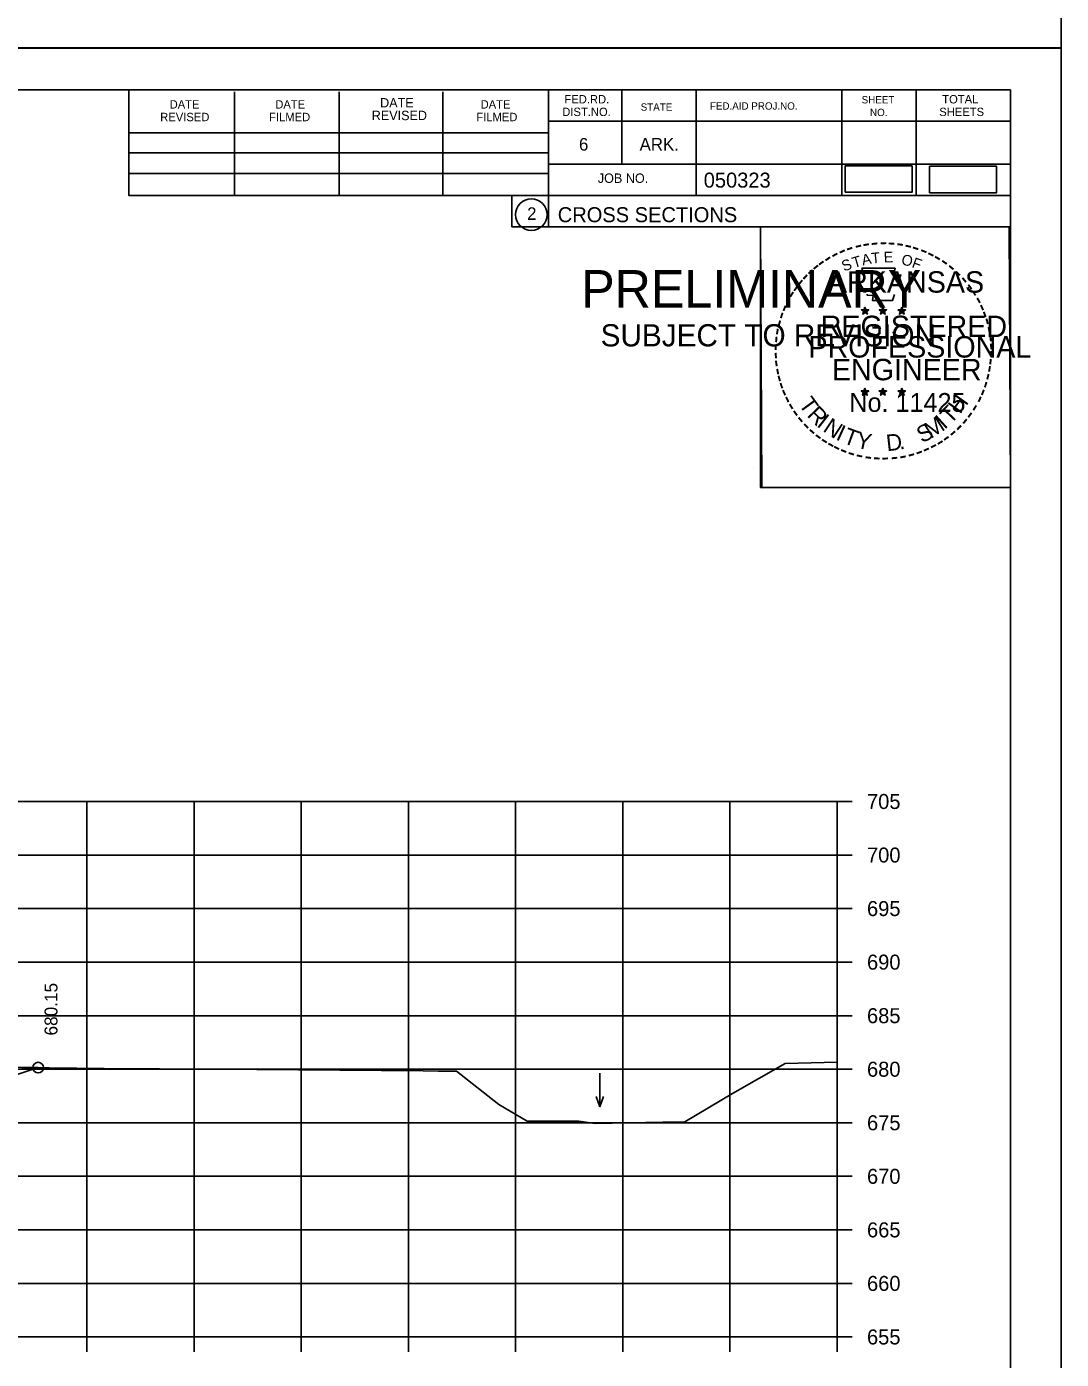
# Model space of a CAD drawing. Extents: x 1360146 to 1361431, y 631444 to 632352.
# Drawn here: x 1360383.1 to 1360479.7, y 631961.7 to 632086.2 of the extents above; entities that cross this region are included whole.
import ezdxf

# ---------------------------------------------------------------- set-up
doc = ezdxf.new("R2010")
doc.units = 0
for name, color, linetype in [('Default', 7, 'Continuous'), ('R_Axis', 7, 'Continuous'), ('R_Axis Annot', 7, 'Continuous'), ('R_Border', 7, 'Continuous'), ('R_Border PE', 7, 'Continuous'), ('R_Border Prem', 7, 'Continuous'), ('R_Exist Surface', 7, 'Continuous'), ('R_Fin Surface', 7, 'Continuous'), ('R_Grid', 7, 'Continuous'), ('R_No Plot', 7, 'Continuous'), ('R_Water Annot', 7, 'Continuous'), ('R_Xsect Elev', 7, 'Continuous')]:
    doc.layers.add(name, color=color, linetype=linetype)

msp = doc.modelspace()

# ---------------------------------------------------------------- linework, layer by layer
at = {"layer": 'Default'}
for points in [[(1360459.52, 632070.7), (1360465.77, 632070.7), (1360465.77, 632073.17), (1360459.52, 632073.17)], [(1360467.41, 632070.66), (1360473.66, 632070.66), (1360473.66, 632073.14), (1360467.41, 632073.14)]]:
    msp.add_lwpolyline(points, close=True, dxfattribs=at)
at = {"layer": 'R_Axis'}
for p, q in [((1360458.77, 631963.82), (1360458.77, 632013.82)), ((1360460.17, 632013.82), (1360458.77, 632013.82)), ((1360460.17, 632008.82), (1360458.77, 632008.82)), ((1360460.17, 632003.82), (1360458.77, 632003.82)), ((1360460.17, 631998.82), (1360458.77, 631998.82)), ((1360460.17, 631993.82), (1360458.77, 631993.82)), ((1360460.17, 631988.82), (1360458.77, 631988.82)), ((1360460.17, 631983.82), (1360458.77, 631983.82)), ((1360460.17, 631978.82), (1360458.77, 631978.82)), ((1360460.17, 631973.82), (1360458.77, 631973.82)), ((1360460.17, 631968.82), (1360458.77, 631968.82)), ((1360178.77, 631963.82), (1360458.77, 631963.82)), ((1360388.77, 631962.42), (1360388.77, 631963.82)), ((1360398.77, 631962.42), (1360398.77, 631963.82)), ((1360408.77, 631962.42), (1360408.77, 631963.82)), ((1360418.77, 631962.42), (1360418.77, 631963.82)), ((1360428.77, 631962.42), (1360428.77, 631963.82)), ((1360438.77, 631962.42), (1360438.77, 631963.82)), ((1360448.77, 631962.42), (1360448.77, 631963.82)), ((1360458.77, 631962.42), (1360458.77, 631963.82)), ((1360460.17, 631963.82), (1360458.77, 631963.82))]:
    msp.add_line(p, q, dxfattribs=at)
at = {"layer": 'R_Border'}
for p, q in [((1360158.77, 632080.28), (1360474.95, 632080.28)), ((1360392.69, 632070.4), (1360392.69, 632080.28)), ((1360402.55, 632070.4), (1360402.55, 632080.08)), ((1360412.31, 632070.4), (1360412.31, 632080.08)), ((1360421.99, 632070.4), (1360421.99, 632080.08)), ((1360431.85, 632080.28), (1360431.85, 632067.48)), ((1360438.69, 632080.28), (1360438.69, 632073.34)), ((1360445.63, 632080.28), (1360445.63, 632070.4)), ((1360459.21, 632080.28), (1360459.21, 632070.4)), ((1360466.15, 632080.28), (1360466.15, 632070.4)), ((1360474.95, 631874.82), (1360474.95, 632080.28)), ((1360474.95, 632077.34), (1360431.85, 632077.34)), ((1360474.95, 632077.36), (1360474.95, 632077.36)), ((1360392.69, 632076.26), (1360431.85, 632076.26)), ((1360392.69, 632074.4), (1360431.85, 632074.4)), ((1360474.95, 632073.34), (1360431.85, 632073.34)), ((1360434.81, 632073.34), (1360474.95, 632073.34)), ((1360392.69, 632070.4), (1360392.69, 632072.46)), ((1360392.69, 632072.46), (1360431.85, 632072.46)), ((1360474.95, 632070.4), (1360392.69, 632070.4)), ((1360431.85, 632067.48), (1360474.95, 632067.48))]:
    msp.add_line(p, q, dxfattribs=at)
msp.add_circle((1360430.24, 632068.62), 1.47, dxfattribs=at)
at = {"layer": 'R_Border PE'}
for p, q in [((1360461.04, 632059.74), (1360461.38, 632059.62)), ((1360461.04, 632059.74), (1360461.29, 632059.69)), ((1360461.04, 632059.74), (1360461.27, 632059.61)), ((1360461.17, 632059.33), (1360461.38, 632059.62)), ((1360461.17, 632059.33), (1360461.29, 632059.57)), ((1360461.38, 632059.99), (1360461.34, 632059.74)), ((1360461.38, 632059.62), (1360461.38, 632059.99)), ((1360461.38, 632059.99), (1360461.43, 632059.74)), ((1360461.73, 632059.74), (1360461.38, 632059.62)), ((1360461.6, 632059.33), (1360461.38, 632059.62)), ((1360461.73, 632059.74), (1360461.45, 632059.69)), ((1360461.6, 632059.33), (1360461.46, 632059.62)), ((1360461.73, 632059.74), (1360461.53, 632059.63)), ((1360462.71, 632059.74), (1360463.05, 632059.62)), ((1360462.71, 632059.74), (1360462.96, 632059.69)), ((1360462.71, 632059.74), (1360462.94, 632059.61)), ((1360462.84, 632059.33), (1360463.05, 632059.62)), ((1360462.84, 632059.33), (1360462.96, 632059.57)), ((1360463.05, 632059.99), (1360463.01, 632059.74)), ((1360463.05, 632059.62), (1360463.05, 632059.99)), ((1360463.05, 632059.99), (1360463.1, 632059.74)), ((1360463.4, 632059.74), (1360463.05, 632059.62)), ((1360463.27, 632059.33), (1360463.05, 632059.62)), ((1360463.4, 632059.74), (1360463.12, 632059.69)), ((1360463.27, 632059.33), (1360463.13, 632059.62)), ((1360463.4, 632059.74), (1360463.2, 632059.63)), ((1360464.47, 632059.72), (1360464.82, 632059.61)), ((1360464.47, 632059.72), (1360464.72, 632059.68)), ((1360464.47, 632059.72), (1360464.71, 632059.6)), ((1360464.6, 632059.32), (1360464.82, 632059.61)), ((1360464.6, 632059.32), (1360464.73, 632059.56)), ((1360464.82, 632059.98), (1360464.78, 632059.73)), ((1360464.82, 632059.61), (1360464.82, 632059.98)), ((1360464.82, 632059.98), (1360464.87, 632059.73)), ((1360465.17, 632059.72), (1360464.82, 632059.61)), ((1360465.03, 632059.32), (1360464.82, 632059.61)), ((1360465.17, 632059.72), (1360464.88, 632059.67)), ((1360465.03, 632059.32), (1360464.89, 632059.61)), ((1360465.17, 632059.72), (1360464.96, 632059.62)), ((1360461.17, 632059.33), (1360461.38, 632059.54)), ((1360461.6, 632059.33), (1360461.38, 632059.54)), ((1360462.84, 632059.33), (1360463.05, 632059.54)), ((1360463.27, 632059.33), (1360463.05, 632059.54)), ((1360464.6, 632059.32), (1360464.82, 632059.53)), ((1360465.03, 632059.32), (1360464.82, 632059.53)), ((1360461.03, 632052.16), (1360461.38, 632052.05)), ((1360461.03, 632052.16), (1360461.28, 632052.12)), ((1360461.03, 632052.16), (1360461.27, 632052.04)), ((1360461.38, 632052.42), (1360461.34, 632052.16)), ((1360461.38, 632052.05), (1360461.38, 632052.42)), ((1360461.38, 632052.42), (1360461.43, 632052.17)), ((1360461.73, 632052.16), (1360461.38, 632052.05)), ((1360461.73, 632052.16), (1360461.44, 632052.11)), ((1360461.73, 632052.16), (1360461.52, 632052.06)), ((1360462.7, 632052.16), (1360463.05, 632052.05)), ((1360462.7, 632052.16), (1360462.95, 632052.12)), ((1360462.7, 632052.16), (1360462.94, 632052.04)), ((1360463.05, 632052.42), (1360463.01, 632052.16)), ((1360463.05, 632052.05), (1360463.05, 632052.42)), ((1360463.05, 632052.42), (1360463.1, 632052.17)), ((1360463.4, 632052.16), (1360463.05, 632052.05)), ((1360463.4, 632052.16), (1360463.11, 632052.11)), ((1360463.4, 632052.16), (1360463.19, 632052.06)), ((1360464.47, 632052.15), (1360464.82, 632052.04)), ((1360464.47, 632052.15), (1360464.72, 632052.11)), ((1360464.47, 632052.15), (1360464.7, 632052.03)), ((1360464.82, 632052.41), (1360464.78, 632052.15)), ((1360464.82, 632052.04), (1360464.82, 632052.41)), ((1360464.82, 632052.41), (1360464.87, 632052.16)), ((1360465.16, 632052.15), (1360464.82, 632052.04)), ((1360465.16, 632052.15), (1360464.88, 632052.1)), ((1360465.16, 632052.15), (1360464.96, 632052.05)), ((1360461.16, 632051.75), (1360461.38, 632052.05)), ((1360461.16, 632051.75), (1360461.29, 632052)), ((1360461.16, 632051.75), (1360461.38, 632051.97)), ((1360461.59, 632051.75), (1360461.38, 632052.05)), ((1360461.59, 632051.75), (1360461.38, 632051.97)), ((1360461.59, 632051.75), (1360461.46, 632052.05)), ((1360462.83, 632051.75), (1360463.05, 632052.05)), ((1360462.83, 632051.75), (1360462.96, 632052)), ((1360462.83, 632051.75), (1360463.05, 632051.97)), ((1360463.26, 632051.75), (1360463.05, 632052.05)), ((1360463.26, 632051.75), (1360463.05, 632051.97)), ((1360463.26, 632051.75), (1360463.13, 632052.05)), ((1360464.6, 632051.74), (1360464.82, 632052.04)), ((1360464.6, 632051.74), (1360464.73, 632051.99)), ((1360464.6, 632051.74), (1360464.81, 632051.96)), ((1360465.03, 632051.74), (1360464.81, 632051.96)), ((1360465.03, 632051.74), (1360464.82, 632052.04)), ((1360465.03, 632051.74), (1360464.89, 632052.04))]:
    msp.add_line(p, q, dxfattribs=at)
for points in [[(1360461.08, 632063.61), (1360461.35, 632062.79)], [(1360464.59, 632062.69), (1360464.73, 632062.98), (1360464.04, 632062.95), (1360464.19, 632063.61), (1360461.08, 632063.61)], [(1360461.57, 632061.19), (1360461.57, 632061.1), (1360462.13, 632061.08), (1360462.08, 632060.61), (1360463.95, 632060.61), (1360464.15, 632061.15)], [(1360461.38, 632059.99), (1360461.6, 632059.33), (1360461.04, 632059.74), (1360461.73, 632059.74), (1360461.17, 632059.33), (1360461.38, 632059.99)], [(1360463.05, 632059.99), (1360463.27, 632059.33), (1360462.71, 632059.74), (1360463.4, 632059.74), (1360462.84, 632059.33), (1360463.05, 632059.99)], [(1360464.82, 632059.98), (1360465.03, 632059.32), (1360464.47, 632059.72), (1360465.17, 632059.72), (1360464.6, 632059.32), (1360464.82, 632059.98)], [(1360461.38, 632052.42), (1360461.59, 632051.75), (1360461.03, 632052.16), (1360461.73, 632052.16), (1360461.16, 632051.75), (1360461.38, 632052.42)], [(1360463.05, 632052.42), (1360463.26, 632051.75), (1360462.7, 632052.16), (1360463.4, 632052.16), (1360462.83, 632051.75), (1360463.05, 632052.42)], [(1360464.82, 632052.41), (1360465.03, 632051.74), (1360464.47, 632052.15), (1360465.16, 632052.15), (1360464.6, 632051.74), (1360464.82, 632052.41)]]:
    msp.add_lwpolyline(points, dxfattribs=at)
for centre, radius in [((1360461.38, 632059.62), 0.172), ((1360461.38, 632059.62), 0.145), ((1360461.38, 632059.62), 0.116), ((1360461.38, 632059.62), 0.0991), ((1360461.38, 632059.62), 0.0747), ((1360461.38, 632059.62), 0.0495), ((1360461.38, 632059.62), 0.0296), ((1360463.05, 632059.62), 0.172), ((1360463.05, 632059.62), 0.145), ((1360463.05, 632059.62), 0.116), ((1360463.05, 632059.62), 0.0991), ((1360463.05, 632059.62), 0.0747), ((1360463.05, 632059.62), 0.0495), ((1360463.05, 632059.62), 0.0296), ((1360464.82, 632059.61), 0.172), ((1360464.82, 632059.61), 0.145), ((1360464.82, 632059.61), 0.116), ((1360464.82, 632059.61), 0.0991), ((1360464.82, 632059.61), 0.0747), ((1360464.82, 632059.61), 0.0495), ((1360464.82, 632059.61), 0.0296), ((1360461.38, 632052.05), 0.172), ((1360461.38, 632052.05), 0.145), ((1360461.38, 632052.05), 0.116), ((1360461.38, 632052.05), 0.0991), ((1360461.38, 632052.05), 0.0747), ((1360461.38, 632052.05), 0.0495), ((1360463.05, 632052.05), 0.172), ((1360463.05, 632052.05), 0.145), ((1360463.05, 632052.05), 0.116), ((1360463.05, 632052.05), 0.0991), ((1360463.05, 632052.05), 0.0747), ((1360463.05, 632052.05), 0.0495), ((1360464.82, 632052.04), 0.172), ((1360464.82, 632052.04), 0.145), ((1360464.82, 632052.04), 0.116), ((1360464.82, 632052.04), 0.0991), ((1360464.82, 632052.04), 0.0747), ((1360461.38, 632052.05), 0.0296), ((1360463.05, 632052.05), 0.0296), ((1360464.82, 632052.04), 0.0495), ((1360464.82, 632052.04), 0.0296)]:
    msp.add_circle(centre, radius, dxfattribs=at)
at = {"layer": 'R_Exist Surface'}
msp.add_lwpolyline([(1360372.41, 631989.11), (1360390.37, 631988.9), (1360400.73, 631988.82), (1360420.15, 631988.66), (1360421.56, 631988.64), (1360423.27, 631988.65), (1360427.22, 631985.53), (1360429.85, 631983.96), (1360434.69, 631983.96), (1360436.21, 631983.76), (1360442.5, 631983.88), (1360444.58, 631983.91), (1360449.01, 631986.55), (1360453.94, 631989.37), (1360458.77, 631989.49)], dxfattribs=at)
at = {"layer": 'R_Fin Surface'}
msp.add_lwpolyline([(1360242.28, 631987.92), (1360261.78, 631981.42), (1360298.75, 631993.74), (1360298.77, 631993.75), (1360304.77, 631995.25), (1360308.77, 631994.95), (1360318.77, 631994.19), (1360328.77, 631993.42), (1360332.77, 631993.12), (1360338.55, 631991.67), (1360338.77, 631991.62), (1360365.47, 631982.72), (1360384.22, 631988.97)], dxfattribs=at)
at = {"layer": 'R_Grid'}
for p, q in [((1360178.77, 632013.82), (1360458.77, 632013.82)), ((1360388.77, 631963.82), (1360388.77, 632013.82)), ((1360398.77, 631963.82), (1360398.77, 632013.82)), ((1360408.77, 631963.82), (1360408.77, 632013.82)), ((1360418.77, 631963.82), (1360418.77, 632013.82)), ((1360428.77, 631963.82), (1360428.77, 632013.82)), ((1360438.77, 631963.82), (1360438.77, 632013.82)), ((1360448.77, 631963.82), (1360448.77, 632013.82)), ((1360458.77, 631963.82), (1360458.77, 632013.82)), ((1360178.77, 632008.82), (1360458.77, 632008.82)), ((1360178.77, 632003.82), (1360458.77, 632003.82)), ((1360178.77, 631998.82), (1360458.77, 631998.82)), ((1360178.77, 631993.82), (1360458.77, 631993.82)), ((1360178.77, 631988.82), (1360458.77, 631988.82)), ((1360178.77, 631983.82), (1360458.77, 631983.82)), ((1360178.77, 631978.82), (1360458.77, 631978.82)), ((1360178.77, 631973.82), (1360458.77, 631973.82)), ((1360178.77, 631968.82), (1360458.77, 631968.82)), ((1360178.77, 631963.82), (1360458.77, 631963.82))]:
    msp.add_line(p, q, dxfattribs=at)
at = {"layer": 'R_No Plot'}
for p, q in [((1360146.37, 632084.18), (1360479.7, 632084.18)), ((1360146.37, 632084.17), (1360479.7, 632084.17)), ((1360450.99, 632045.02), (1360450.99, 632045.02))]:
    msp.add_line(p, q, dxfattribs=at)
for points in [[(1360146.36, 632297.51), (1360479.7, 632297.51), (1360479.7, 632084.17), (1360146.36, 632084.17)], [(1360146.36, 632084.17), (1360479.7, 632084.17), (1360479.7, 631870.84), (1360146.36, 631870.84)], [(1360392.69, 632080.28), (1360392.69, 632070.4), (1360428.42, 632070.4), (1360428.42, 632067.48), (1360451.62, 632067.48), (1360451.62, 632043.15), (1360474.95, 632043.15), (1360474.95, 631874.82), (1360158.77, 631874.82), (1360158.77, 632080.28)], [(1360451.62, 632067.48), (1360474.83, 632067.48), (1360474.95, 632043.15), (1360451.74, 632043.15)], [(1360348.56, 631988.36), (1360350.29, 631988.65), (1360365.94, 631989.14), (1360372.41, 631989.11), (1360384.22, 631988.97), (1360365.47, 631982.72)]]:
    msp.add_lwpolyline(points, close=True, dxfattribs=at)
msp.add_circle((1360384.22, 631988.97), 0.5, dxfattribs=at)
at = {"layer": 'R_Water Annot'}
for p, q in [((1360436.63, 631988.44), (1360436.63, 631985.3)), ((1360436.63, 631985.3), (1360436.28, 631986.26)), ((1360436.63, 631985.3), (1360436.98, 631986.26))]:
    msp.add_line(p, q, dxfattribs=at)

# ---------------------------------------------------------------- texts
at = {"layer": 'R_Axis Annot'}
for s, p in [('705', (1360461.57, 632013.12)), ('700', (1360461.57, 632008.12)), ('695', (1360461.57, 632003.12)), ('690', (1360461.57, 631998.12)), ('685', (1360461.57, 631993.12)), ('680', (1360461.57, 631988.12)), ('675', (1360461.57, 631983.12)), ('670', (1360461.57, 631978.12)), ('665', (1360461.57, 631973.12)), ('660', (1360461.57, 631968.12)), ('655', (1360461.57, 631963.12))]:
    msp.add_text(s, height=1.4, dxfattribs=at).set_placement(p)
at = {"layer": 'R_Border'}
for s, height, p in [('DATE', 0.879, (1360416.13, 632078.62)), ('FED.RD.', 0.782, (1360433.33, 632079)), ('SHEET', 0.684, (1360461.07, 632079)), ('TOTAL', 0.782, (1360468.59, 632079)), ('DATE', 0.782, (1360396.49, 632078.52)), ('DATE', 0.782, (1360406.35, 632078.52)), ('REVISED', 0.879, (1360415.35, 632077.44)), ('DATE', 0.782, (1360425.51, 632078.52)), ('DIST.NO.', 0.782, (1360433.13, 632077.82)), ('STATE', 0.684, (1360440.45, 632078.32)), ('FED.AID PROJ.NO.', 0.684, (1360446.91, 632078.42)), ('NO.', 0.684, (1360461.85, 632077.82)), ('SHEETS', 0.782, (1360468.31, 632077.82)), ('REVISED', 0.782, (1360395.61, 632077.34)), ('FILMED', 0.782, (1360405.77, 632077.34)), ('FILMED', 0.782, (1360425.11, 632077.34)), ('6', 1.17, (1360434.69, 632074.6)), ('ARK.', 1.172, (1360440.35, 632074.6)), ('JOB NO.', 0.879, (1360436.45, 632071.58)), ('050323', 1.4, (1360446.33, 632071.14)), ('2', 1.17, (1360429.85, 632068.13)), ('CROSS SECTIONS', 1.4, (1360432.71, 632067.91))]:
    msp.add_text(s, height=height, rotation=360, dxfattribs=at).set_placement(p)
at = {"layer": 'R_Border PE'}
for s, height, rotation, p in [('-', 1.6, 13.6301, (1360460.57, 632064.98)), ('-', 1.6, 10.2193, (1360461.25, 632065.14)), ('-', 1.6, 5.8968, (1360461.98, 632065.25)), ('-', 1.6, 0.1862, (1360462.75, 632065.33)), ('-', 1.6, 357.743, (1360463.48, 632065.31)), ('-', 1.6, 352.1617, (1360464.22, 632065.26)), ('-', 1.6, 347.2049, (1360464.94, 632065.14)), ('-', 1.6, 34.0636, (1360457.96, 632063.78)), ('-', 1.6, 28.7918, (1360458.56, 632064.15)), ('-', 1.6, 24.3072, (1360459.19, 632064.47)), ('-', 1.6, 19.1761, (1360459.82, 632064.74)), ('T', 1, 16.4036, (1360460.35, 632063.62)), ('A', 1, 11.2132, (1360461.17, 632063.87)), ('T', 1, 6.0228, (1360462.02, 632064.04)), ('E', 1, 0.8323, (1360463.13, 632064.15)), ('O', 1, 350.4515, (1360464.73, 632063.94)), ('F', 1, 340.0707, (1360465.68, 632063.71)), ('-', 1.6, 342.3362, (1360465.57, 632064.99)), ('-', 1.6, 337.8551, (1360466.31, 632064.76)), ('-', 1.6, 334.1211, (1360466.94, 632064.49)), ('-', 1.6, 329.6409, (1360467.52, 632064.21)), ('-', 1.6, 42.9622, (1360456.47, 632062.59)), ('-', 1.6, 38.9507, (1360456.91, 632063.01)), ('-', 1.6, 36.2317, (1360457.38, 632063.39)), ('ARKANSAS', 2, 360, (1360457.93, 632061.33)), ('S', 1, 21.594, (1360459.43, 632063.29)), ('-', 1.6, 325.8627, (1360468.16, 632063.85)), ('-', 1.6, 320.5297, (1360468.77, 632063.42)), ('-', 1.6, 315.5786, (1360469.37, 632062.94)), ('-', 1.6, 50.6142, (1360455.62, 632061.63)), ('-', 1.6, 48.423, (1360456.03, 632062.12)), ('-', 1.6, 309.8797, (1360469.94, 632062.39)), ('-', 1.6, 306.6522, (1360470.47, 632061.78)), ('-', 1.6, 58.0706, (1360454.88, 632060.54)), ('-', 1.6, 54.2325, (1360455.21, 632061.06)), ('-', 1.4, 303.6753, (1360470.95, 632061.22)), ('-', 1.6, 299.6684, (1360471.27, 632060.61)), ('-', 1.6, 67.7743, (1360454.31, 632059.31)), ('-', 1.6, 62.8713, (1360454.57, 632059.92)), ('DWB', 0.01, 360, (1360461.37, 632059.62)), ('DWB', 0.01, 360, (1360463.04, 632059.62)), ('DWB', 0.01, 360, (1360464.81, 632059.61)), ('-', 1.6, 294.6628, (1360471.59, 632060)), ('-', 1.6, 290.5728, (1360471.85, 632059.42)), ('-', 1.6, 75.461, (1360453.9, 632057.97)), ('-', 1.6, 72.3945, (1360454.09, 632058.68)), ('REGISTERED', 2, 360, (1360457.25, 632057.18)), ('-', 1.6, 285.1233, (1360472.09, 632058.84)), ('-', 1.6, 85.1863, (1360453.69, 632056.56)), ('-', 1.6, 81.2013, (1360453.76, 632057.25)), ('PROFESSIONAL', 2, 360, (1360456.1, 632055.27)), ('-', 1.6, 280.5493, (1360472.29, 632058.1)), ('-', 1.6, 276.5962, (1360472.45, 632057.33)), ('-', 1.6, 89.0622, (1360453.66, 632055.86)), ('-', 1.6, 274.3301, (1360472.51, 632056.61)), ('-', 1.6, 269.9407, (1360472.54, 632055.98)), ('-', 1.6, 94.1959, (1360453.7, 632055.14)), ('-', 1.6, 98.9479, (1360453.77, 632054.47)), ('ENGINEER', 2, 360, (1360458.29, 632053.15)), ('-', 1.6, 263.5172, (1360472.52, 632055.31)), ('-', 1.6, 101.7149, (1360453.91, 632053.74)), ('-', 1.6, 105.4578, (1360454.07, 632053.14)), ('-', 1.6, 255.7626, (1360472.34, 632053.98)), ('-', 1.6, 260.9953, (1360472.45, 632054.66)), ('-', 1.6, 109.0874, (1360454.28, 632052.51)), ('-', 1.6, 114.0643, (1360454.54, 632051.92)), ('-', 1.6, 247.8887, (1360471.94, 632052.58)), ('-', 1.6, 252.8681, (1360472.16, 632053.26)), ('-', 1.6, 115.7289, (1360454.84, 632051.3)), ('-', 1.6, 120.4471, (1360455.2, 632050.71)), ('T', 1.54, 306.0406, (1360455.14, 632050.89)), ('No. 11425', 1.757, 360, (1360459.92, 632050.2)), ('DWB', 0.01, 360, (1360461.37, 632052.05)), ('DWB', 0.01, 360, (1360463.04, 632052.05)), ('DWB', 0.01, 360, (1360464.8, 632052.04)), ('T', 1.54, 46.6444, (1360469.37, 632048.98)), ('H', 1.54, 54.6088, (1360470.26, 632049.92)), ('-', 1.6, 239.0712, (1360471.28, 632051.2)), ('-', 1.6, 244.6197, (1360471.68, 632051.96)), ('-', 1.6, 125.8934, (1360455.6, 632050.15)), ('-', 1.6, 130.7181, (1360456.06, 632049.6)), ('R', 1.54, 314.005, (1360455.9, 632049.84)), ('I', 1.54, 321.9694, (1360456.8, 632048.91)), ('N', 1.54, 326.5002, (1360457.37, 632048.44)), ('M', 1.54, 32.6563, (1360467.52, 632047.66)), ('I', 1.54, 42.1136, (1360468.81, 632048.5)), ('-', 1.6, 233.8452, (1360470.88, 632050.55)), ('-', 1.6, 134.2238, (1360456.58, 632049.05)), ('-', 1.6, 138.9338, (1360457.11, 632048.59)), ('I', 1.54, 335.3603, (1360458.58, 632047.65)), ('T', 1.54, 339.8912, (1360459.24, 632047.32)), ('Y', 1.54, 347.8556, (1360460.46, 632046.88)), ('S', 1.54, 26.9312, (1360466.69, 632047.25)), ('-', 1.6, 221.0851, (1360469.45, 632048.91)), ('-', 1.6, 225.7653, (1360469.97, 632049.42)), ('-', 1.6, 231.2538, (1360470.45, 632049.98)), ('-', 1.6, 144.6463, (1360457.66, 632048.18)), ('-', 1.6, 148.0898, (1360458.22, 632047.81)), ('-', 1.6, 151.5704, (1360458.8, 632047.49)), ('D', 1.54, 6.3969, (1360463.44, 632046.52)), ('-', 1.6, 207.3568, (1360467.81, 632047.71)), ('-', 1.6, 212.2491, (1360468.37, 632048.05)), ('-', 1.6, 215.7363, (1360468.9, 632048.44)), ('-', 1.6, 154.6002, (1360459.32, 632047.24)), ('-', 1.6, 158.5612, (1360459.95, 632046.99)), ('-', 1.6, 162.7983, (1360460.63, 632046.77)), ('-', 1.6, 167.5555, (1360461.35, 632046.61)), ('-', 1.6, 173.1155, (1360462.12, 632046.5)), ('-', 1.6, 176.5183, (1360462.87, 632046.45)), ('-', 1.6, 181.5918, (1360463.61, 632046.47)), ('-', 1.6, 185.8167, (1360464.42, 632046.54)), ('-', 1.6, 191.2858, (1360465.16, 632046.67)), ('.', 1.54, 13.7642, (1360464.63, 632046.65)), ('-', 1.6, 195.4743, (1360465.89, 632046.87)), ('-', 1.6, 200.7184, (1360466.56, 632047.11)), ('-', 1.6, 204.2516, (1360467.18, 632047.39))]:
    msp.add_text(s, height=height, rotation=rotation, dxfattribs=at).set_placement(p)
at = {"layer": 'R_Border Prem'}
for s, height, p in [('PRELIMINARY', 3.5, (1360434.9, 632059.94)), ('DWB', 0.01, (1360435.65, 632061.79)), ('SUBJECT TO REVISION', 2.0751, (1360436.71, 632056.31))]:
    msp.add_text(s, height=height, rotation=360, dxfattribs=at).set_placement(p)
at = {"layer": 'R_Xsect Elev'}
msp.add_text('680.15', height=1.2, rotation=90, dxfattribs=at).set_placement((1360386.02, 631991.97))

doc.saveas('drawing.dxf')
